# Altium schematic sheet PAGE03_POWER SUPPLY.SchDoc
size 330 x 203 mm
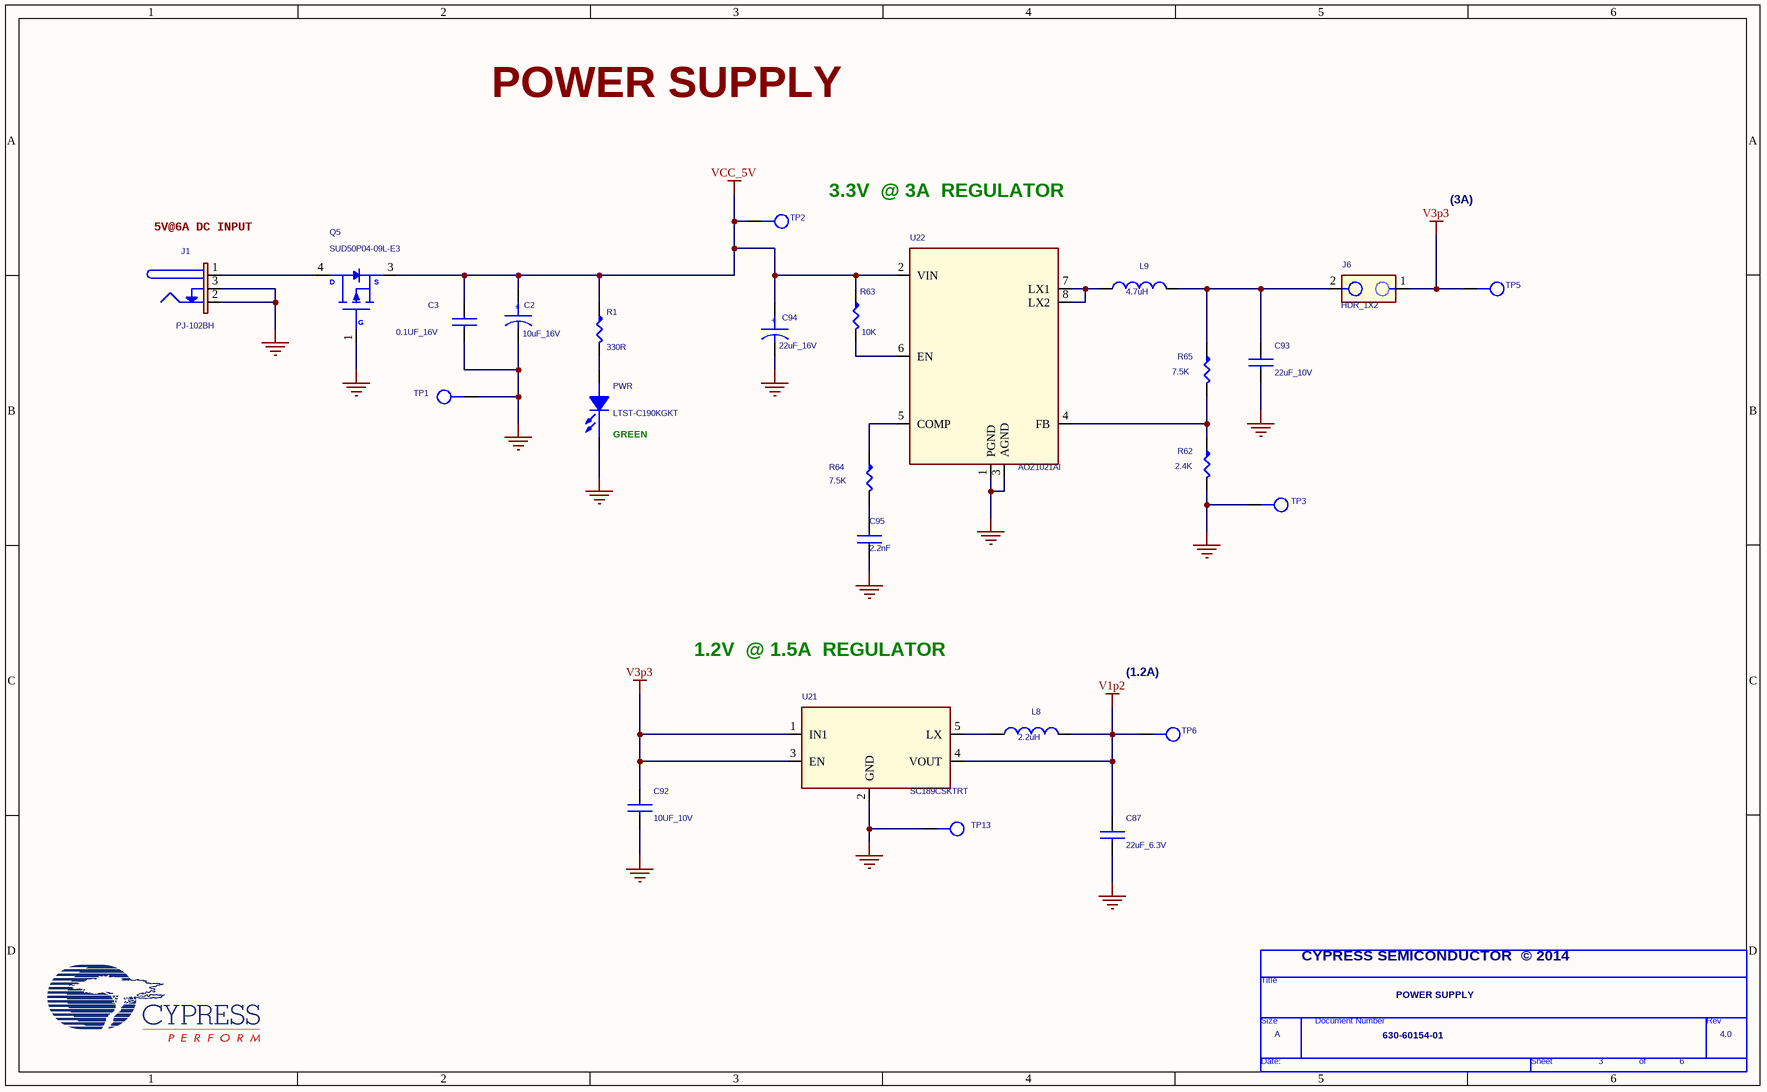
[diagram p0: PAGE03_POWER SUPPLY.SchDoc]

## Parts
*  Page Count: 6  Page Number: 3  Page Size: A  Title: POWER SUPPLY  RevCode: 4.0  Doc: 630-60154-01  (hidden comment: TitleBlock0)  (graphical)
C2  10uF_16V  [CAPMP3216X180M]
C3  0.1UF_16V  [CAPC1005X56M]
C87  22uF_6.3V  [CAPC3216X100M]
C92  10UF_10V  [CAPC2012X145M]
C93  22uF_10V  [CAPC3216X100M]
C94  22uF_16V  [CAPCP3216X100M]
C95  2.2nF  [CAPC2112X70M]
J1  PJ-102BH  [CUI_PJ-102BH]
J6  HDR_1X2  [SAMTEC_TSW-102-08-G-S]
L8  2.2uH  [INDP3225X240M]
L9  4.7uH  [IND_NR6028T4R7M]
PWR  LTST-C190KGKT  [LEDC1608X80M]
Q5  SUD50P04-09L-E3  [TO228P991X238-3M]
R1  330R  [RESC1608X55M]
R62  2.4K  [RESC1608X55M]
R63  10K  [RESC1608X55M]
R64  7.5K  [RESC1608X55M]
R65  7.5K  [RESC1608X55M]
TP1  TP_BLACK  [KEYSTONE_5000]  (value not drawn)
TP2  TP_RED  [KEYSTONE_5000]  (value not drawn)
TP3  TP_BLACK  [KEYSTONE_5000]  (value not drawn)
TP5  TP_RED  [KEYSTONE_5000]  (value not drawn)
TP6  TP_RED  [KEYSTONE_5000]  (value not drawn)
TP13  TP_BLACK  [KEYSTONE_5000]  (value not drawn)
U21  SC189CSKTRT  [SOT95P280X145-5M]
U22  AOZ1021AI  [SOIC127P600X175-8M]

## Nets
GND: C2.2 C3.2 C87.2 C92.2 C93.2 C94.2 C95.1 J1.2 J1.3 PWR.2(CATHODE) Q5.1(G) R62.2 TP1.1(TP) TP3.1(TP) TP13.1(TP) U21.2(GND) U22.1(PGND) U22.3(AGND)
V1p2: C87.1 L8.2 TP6.1(TP) U21.4(VOUT)
V3p3: C92.1 J6.1 TP5.1(TP) U21.1(IN1) U21.3(EN)
VCC_5V: C2.1 C3.1 C94.1 Q5.3(S) R1.1 R63.1 TP2.1(TP) U22.2(VIN)
NetC93_1: C93.1 J6.2 L9.2 R65.1
NetC95_2: C95.2 R64.2
NetJ1_1: J1.1 Q5.4(D)
NetL8_1: L8.1 U21.5(LX)
NetL9_1: L9.1 U22.7(LX1) U22.8(LX2)
NetPWR_1: PWR.1(ANODE) R1.2
NetR62_1: R62.1 R65.2 U22.4(FB)
NetR63_2: R63.2 U22.6(EN)
NetR64_1: R64.1 U22.5(COMP)

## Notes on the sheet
- POWER SUPPLY
- (near J1) 5V@6A DC INPUT
- 3.3V  @ 3A  REGULATOR
- (3A)
- (near PWR) GREEN
- 1.2V  @ 1.5A  REGULATOR
- (1.2A)
- (near *) CYPRESS SEMICONDUCTOR  © 2014

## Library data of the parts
C2 = CAP POL: CAP TANT 10UF 16V 20% 1206; Part Number: TAJA106M016RNJ; Manufacturer: AVX Corporation
C3 C87 C92 C93 = CAPACITOR NON-POL
C94 = CAP POL: CAP TANT 22UF 16V 10% 1206; Manufacturer: Nichicon; Part Number: F951C226KQAAQ2
C95 = CAPACITOR NON-POL: CAP CER 2200PF 50V 10% X7R 0805; Manufacturer: Yageo; Part Number: CC0805KRX7R9BB222; Num Pins: 2
J1 = PowerJack: CONN PWR JACK 2.5X5.5MM HIGH CUR; Manufacturer: CUI Inc
J6 = HEADER_1x2: Manufacturer: Samtec Inc; Part Number: TSW-102-08-G-S
L8 = INDUCTOR: INDUCTOR 2.2UH 1.20A 20% 1210; Part Number: NLCV32T-2R2M-PFR; Manufacturer: TDK Corporation
L9 = INDUCTOR: INDUCTOR 4.7UH 2.7A 20% SMD; Part Number: NR6028T4R7M; Manufacturer: Taiyo Yuden
PWR = LED: LED GREEN CLEAR 0603 SMD; Manufacturer: Lite-On; Voltage Rating: 2V; CURRENT: 20mA
R1 = R_Dup1: RES 180 OHM 1/16W 1% 0402 SMD; Manufacturer: Vishay; Part Number: CRCW0402180RFKED
R62 = R_Dup1: RES 2.4K OHM 1/10W 1% 0603 SMD; Manufacturer: Panasonic - ECG; Part Number: ERJ-3EKF2401V
R63 = R_Dup1: RES 10.0K OHM 1/10W 1% 0603 SMD; Manufacturer: Panasonic - ECG; Part Number: ERJ-3EKF1002V
R64 = R_Dup1: RES 7.5K OHM 1/10W 1% 0603 SMD; Part Number: ERJ-3EKF7501V; Manufacturer: Panasonic - ECG
R65 = R_Dup1: RES 7.5K OHM 1/10W 1% 0603 SMD; Manufacturer: Panasonic - ECG; Part Number: ERJ-3EKF7501V
TP1 = TP: TEST POINT PC MINI .040"D BLACK; Manufacturer: Keystone; PART_NUMBER: 5000
TP2 TP5 = TP: TEST POINT PC MINI .040"D RED; PART_NUMBER: 5000; Manufacturer: Keystone
TP3 = TP: TEST POINT PC MINI .040"D BLACK; PART_NUMBER: 5000; Manufacturer: Keystone
TP6 = TP: TEST POINT PC MINI .040"D RED; Manufacturer: Keystone; Part Number: 5000
TP13 = TP: TEST POINT PC MINI .040"D BLACK; Part Number: 5000; Manufacturer: Keystone
U21 = SC189CSKTRT: IC REG BUCK SYNC 1.2V SOT23-5; Manufacturer: Semtech
U22 = AOZ1021AI: IC REG BUCK SYNC ADJ 3A 8SOIC; Manufacturer: Alpha & Omega Semiconductor Inc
